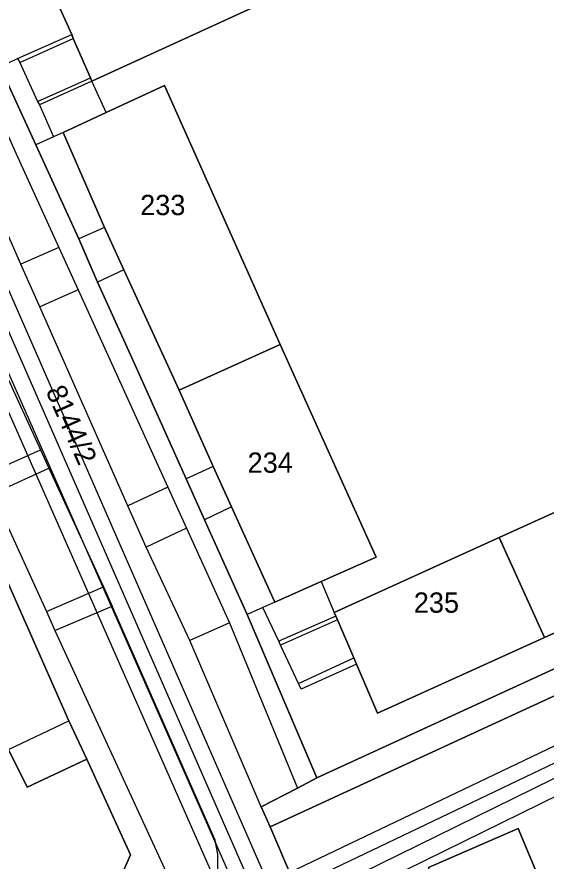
# Model space of a CAD drawing. Extents: x -264070 to -262271, y -1238894 to -1238141.
# Drawn here: x -263532.4 to -263480.2, y -1238522.1 to -1238438.9 of the extents above; entities that cross this region are included whole.
import ezdxf

# ---------------------------------------------------------------- set-up
doc = ezdxf.new("R2010")
doc.units = 0
for name, color, linetype in [('body_kn', 7, 'Continuous'), ('kladpar_druhypozemkov', 7, 'Continuous'), ('kladpar_hranice', 7, 'Continuous'), ('kladpar_parcelnecisla', 7, 'Continuous'), ('kladpar_plochy', 7, 'Continuous'), ('tarchy_linie', 7, 'Continuous'), ('zappar_hrandruhpozemk', 7, 'Continuous')]:
    doc.layers.add(name, color=color, linetype=linetype)

msp = doc.modelspace()

# ---------------------------------------------------------------- linework, layer by layer
at = {"layer": 'body_kn'}
for p, q in [((-263527, -1238440.63), (-263527, -1238440.63)), ((-263526.85, -1238441.05), (-263526.85, -1238441.05)), ((-263532.35, -1238443.02), (-263532.35, -1238443.02)), ((-263532.35, -1238443.02), (-263532.35, -1238443.02)), ((-263532.13, -1238443.41), (-263532.13, -1238443.41)), ((-263525.15, -1238444.9), (-263525.15, -1238444.9)), ((-263525, -1238445.24), (-263525, -1238445.24)), ((-263525, -1238445.24), (-263525, -1238445.24)), ((-263517.86, -1238445.68), (-263517.86, -1238445.68)), ((-263530.38, -1238447.26), (-263530.38, -1238447.26)), ((-263530.19, -1238447.56), (-263530.19, -1238447.56)), ((-263530.19, -1238447.56), (-263530.19, -1238447.56)), ((-263523.6, -1238448.33), (-263523.6, -1238448.33)), ((-263523.6, -1238448.33), (-263523.6, -1238448.33)), ((-263528.79, -1238450.73), (-263528.79, -1238450.73)), ((-263527.83, -1238450.32), (-263527.83, -1238450.32)), ((-263527.83, -1238450.32), (-263527.83, -1238450.32)), ((-263530.53, -1238451.52), (-263530.53, -1238451.52)), ((-263523.77, -1238459.66), (-263523.77, -1238459.66)), ((-263523.77, -1238459.66), (-263523.77, -1238459.66)), ((-263526.3, -1238460.78), (-263526.3, -1238460.78)), ((-263528.28, -1238461.63), (-263528.28, -1238461.63)), ((-263528.28, -1238461.63), (-263528.28, -1238461.63)), ((-263532.01, -1238463.29), (-263532.01, -1238463.29)), ((-263521.86, -1238463.86), (-263521.86, -1238463.86)), ((-263521.86, -1238463.86), (-263521.86, -1238463.86)), ((-263524.45, -1238465.05), (-263524.45, -1238465.05)), ((-263524.45, -1238465.05), (-263524.45, -1238465.05)), ((-263526.38, -1238465.8), (-263526.38, -1238465.8)), ((-263530.15, -1238467.48), (-263530.15, -1238467.48)), ((-263530.15, -1238467.48), (-263530.15, -1238467.48)), ((-263506.44, -1238471.22), (-263506.44, -1238471.22)), ((-263506.44, -1238471.22), (-263506.44, -1238471.22)), ((-263521.05, -1238472.6), (-263521.05, -1238472.6)), ((-263516.41, -1238475.7), (-263516.41, -1238475.7)), ((-263530.08, -1238481.6), (-263530.08, -1238481.6)), ((-263530.08, -1238481.6), (-263530.08, -1238481.6)), ((-263529.25, -1238483.41), (-263529.25, -1238483.41)), ((-263513.04, -1238483.23), (-263513.04, -1238483.23)), ((-263513.04, -1238483.23), (-263513.04, -1238483.23)), ((-263515.71, -1238484.44), (-263515.71, -1238484.44)), ((-263517.52, -1238485.28), (-263517.52, -1238485.28)), ((-263521.45, -1238487.1), (-263521.45, -1238487.1)), ((-263521.45, -1238487.1), (-263521.45, -1238487.1)), ((-263511.23, -1238487.21), (-263511.23, -1238487.21)), ((-263511.23, -1238487.21), (-263511.23, -1238487.21)), ((-263513.9, -1238488.48), (-263513.9, -1238488.48)), ((-263515.69, -1238489.32), (-263515.69, -1238489.32)), ((-263515.69, -1238489.32), (-263515.69, -1238489.32)), ((-263484.82, -1238490.23), (-263484.82, -1238490.23)), ((-263484.82, -1238490.23), (-263484.82, -1238490.23)), ((-263519.64, -1238491.18), (-263519.64, -1238491.18)), ((-263496.95, -1238492.17), (-263496.95, -1238492.17)), ((-263502.38, -1238494.57), (-263502.38, -1238494.57)), ((-263502.38, -1238494.57), (-263502.38, -1238494.57)), ((-263523.88, -1238495.1), (-263523.88, -1238495.1)), ((-263523.01, -1238496.99), (-263523.01, -1238496.99)), ((-263508.14, -1238497.14), (-263508.14, -1238497.14)), ((-263508.14, -1238497.14), (-263508.14, -1238497.14)), ((-263506.96, -1238496.61), (-263506.96, -1238496.61)), ((-263506.96, -1238496.61), (-263506.96, -1238496.61)), ((-263529.5, -1238497.53), (-263529.5, -1238497.53)), ((-263529.5, -1238497.53), (-263529.5, -1238497.53)), ((-263509.7, -1238497.82), (-263509.7, -1238497.82)), ((-263501.1, -1238497.63), (-263501.1, -1238497.63)), ((-263500.94, -1238498), (-263500.94, -1238498)), ((-263500.94, -1238498), (-263500.94, -1238498)), ((-263511.45, -1238498.64), (-263511.45, -1238498.64)), ((-263511.45, -1238498.64), (-263511.45, -1238498.64)), ((-263500.79, -1238498.36), (-263500.79, -1238498.36)), ((-263500.79, -1238498.36), (-263500.79, -1238498.36)), ((-263528.65, -1238499.39), (-263528.65, -1238499.39)), ((-263528.65, -1238499.39), (-263528.65, -1238499.39)), ((-263515.35, -1238500.38), (-263515.35, -1238500.38)), ((-263515.35, -1238500.38), (-263515.35, -1238500.38)), ((-263506.58, -1238500.45), (-263506.58, -1238500.45)), ((-263506.58, -1238500.45), (-263506.58, -1238500.45)), ((-263480.36, -1238500.09), (-263480.36, -1238500.09)), ((-263506.4, -1238500.84), (-263506.4, -1238500.84)), ((-263506.4, -1238500.84), (-263506.4, -1238500.84)), ((-263499.16, -1238502.11), (-263499.16, -1238502.11)), ((-263498.91, -1238502.71), (-263498.91, -1238502.71)), ((-263498.91, -1238502.71), (-263498.91, -1238502.71)), ((-263504.63, -1238504.62), (-263504.63, -1238504.62)), ((-263504.37, -1238505.19), (-263504.37, -1238505.19)), ((-263496.82, -1238507.56), (-263496.82, -1238507.56)), ((-263527.27, -1238508.32), (-263527.27, -1238508.32)), ((-263525.52, -1238512.09), (-263525.52, -1238512.09)), ((-263502.82, -1238513.93), (-263502.82, -1238513.93)), ((-263531.4, -1238514.86), (-263531.4, -1238514.86)), ((-263531.4, -1238514.86), (-263531.4, -1238514.86)), ((-263504.72, -1238514.94), (-263504.72, -1238514.94)), ((-263508.31, -1238516.78), (-263508.31, -1238516.78)), ((-263508.31, -1238516.78), (-263508.31, -1238516.78)), ((-263507.42, -1238518.77), (-263507.42, -1238518.77)), ((-263482.95, -1238518.92), (-263482.95, -1238518.92)), ((-263512.85, -1238520.09), (-263512.85, -1238520.09)), ((-263512.58, -1238521.47), (-263512.58, -1238521.47)), ((-263521.21, -1238521.51), (-263521.21, -1238521.51))]:
    msp.add_line(p, q, dxfattribs=at)
at = {"layer": 'kladpar_druhypozemkov'}
for p, q in [((-263517.76, -1238456.8), (-263517.76, -1238456.8)), ((-263530.05, -1238474.62), (-263530.05, -1238474.62)), ((-263507.71, -1238481.8), (-263507.71, -1238481.8)), ((-263491.11, -1238495.4), (-263491.11, -1238495.4))]:
    msp.add_line(p, q, dxfattribs=at)
at = {"layer": 'kladpar_hranice'}
for points in [[(-263493.11, -1238415.76), (-263470.58, -1238405.55), (-263468.15, -1238404.43), (-263451.66, -1238396.9), (-263450.61, -1238399.35), (-263426.11, -1238459), (-263424.74, -1238462.35), (-263423.38, -1238465.68), (-263422.04, -1238468.97), (-263420.59, -1238472.47), (-263419.19, -1238475.61), (-263423.39, -1238477.55), (-263433.56, -1238482.16), (-263502.82, -1238513.93), (-263509.7, -1238497.82), (-263513.9, -1238488.48), (-263515.71, -1238484.44), (-263521.05, -1238472.6), (-263524.45, -1238465.05), (-263526.3, -1238460.78), (-263530.53, -1238451.52), (-263534.06, -1238443.82)], [(-263474.15, -1238422.1), (-263452.92, -1238412.46), (-263454.93, -1238407.94), (-263450.88, -1238406.06), (-263453.34, -1238400.63), (-263467.07, -1238406.77), (-263469.48, -1238407.89), (-263478.58, -1238412.08), (-263491.98, -1238418.16), (-263494.64, -1238419.36), (-263503.63, -1238423.51), (-263517.17, -1238429.65), (-263519.77, -1238430.84), (-263529.46, -1238435.2), (-263527, -1238440.63), (-263526.85, -1238441.05), (-263525.15, -1238444.9), (-263525, -1238445.24), (-263499.27, -1238433.43), (-263474.15, -1238422.1)], [(-263517.17, -1238429.65), (-263503.63, -1238423.51), (-263499.27, -1238433.43), (-263525, -1238445.24), (-263525.15, -1238444.9), (-263526.85, -1238441.05), (-263527, -1238440.63), (-263529.46, -1238435.2), (-263519.77, -1238430.84), (-263517.17, -1238429.65)], [(-263521.92, -1238523.16), (-263521.21, -1238521.51), (-263525.52, -1238512.09), (-263527.27, -1238508.32), (-263533.94, -1238493.27), (-263540.78, -1238478.21), (-263547.35, -1238463.4), (-263555.82, -1238444.87), (-263548.49, -1238441.32), (-263542.86, -1238438.6), (-263537.75, -1238436.14), (-263534.06, -1238443.82), (-263530.53, -1238451.52), (-263526.3, -1238460.78), (-263524.45, -1238465.05)], [(-263496.95, -1238492.17), (-263506.44, -1238471.22), (-263517.86, -1238445.68), (-263523.6, -1238448.33), (-263527.83, -1238450.32), (-263523.77, -1238459.66), (-263521.86, -1238463.86), (-263516.41, -1238475.7), (-263513.04, -1238483.23), (-263511.23, -1238487.21), (-263506.96, -1238496.61), (-263502.38, -1238494.57), (-263496.95, -1238492.17)], [(-263506.44, -1238471.22), (-263516.41, -1238475.7), (-263521.86, -1238463.86), (-263523.77, -1238459.66), (-263527.83, -1238450.32), (-263523.6, -1238448.33), (-263517.86, -1238445.68), (-263506.44, -1238471.22)], [(-263524.45, -1238465.05), (-263521.05, -1238472.6), (-263515.71, -1238484.44), (-263513.9, -1238488.48), (-263509.7, -1238497.82), (-263502.82, -1238513.93), (-263504.72, -1238514.94), (-263508.31, -1238516.78), (-263507.42, -1238518.77), (-263505.24, -1238523.86)], [(-263459.89, -1238490.81), (-263441.83, -1238482.63), (-263424.56, -1238474.9), (-263428.88, -1238464.9), (-263446.37, -1238472.82), (-263464.41, -1238480.99), (-263484.82, -1238490.23), (-263501.1, -1238497.63), (-263500.94, -1238498), (-263500.79, -1238498.36), (-263499.16, -1238502.11), (-263498.91, -1238502.71), (-263496.82, -1238507.56), (-263480.36, -1238500.09), (-263459.89, -1238490.81)], [(-263506.44, -1238471.22), (-263496.95, -1238492.17), (-263502.38, -1238494.57), (-263506.96, -1238496.61), (-263511.23, -1238487.21), (-263513.04, -1238483.23), (-263516.41, -1238475.7), (-263506.44, -1238471.22)], [(-263464.41, -1238480.99), (-263459.89, -1238490.81), (-263480.36, -1238500.09), (-263484.82, -1238490.23), (-263464.41, -1238480.99)], [(-263433.56, -1238482.16), (-263432.65, -1238484.31), (-263507.42, -1238518.77), (-263508.31, -1238516.78), (-263504.72, -1238514.94), (-263502.82, -1238513.93), (-263433.56, -1238482.16)], [(-263505.24, -1238523.86), (-263507.42, -1238518.77), (-263432.65, -1238484.31)], [(-263484.82, -1238490.23), (-263480.36, -1238500.09), (-263496.82, -1238507.56), (-263498.91, -1238502.71), (-263499.16, -1238502.11), (-263500.79, -1238498.36), (-263500.94, -1238498), (-263501.1, -1238497.63), (-263484.82, -1238490.23)], [(-263533.94, -1238493.27), (-263527.27, -1238508.32), (-263525.52, -1238512.09), (-263531.4, -1238514.86), (-263533.22, -1238511.14), (-263537.53, -1238513.17), (-263538.52, -1238513.67), (-263541.73, -1238506.78), (-263543.34, -1238507.57), (-263545, -1238504.22), (-263543.4, -1238503.43), (-263545.4, -1238499.35), (-263545.75, -1238499.56), (-263546.04, -1238498.93), (-263533.94, -1238493.27)], [(-263531.4, -1238514.86), (-263525.52, -1238512.09), (-263521.21, -1238521.51), (-263521.92, -1238523.16), (-263546.82, -1238534.88), (-263551.68, -1238524.8), (-263543.28, -1238520.85), (-263542.79, -1238521.91), (-263540.78, -1238520.99), (-263541.05, -1238518.89), (-263541.02, -1238518.35), (-263540.78, -1238517.93), (-263540.39, -1238517.72), (-263539.94, -1238517.66), (-263539.28, -1238517.73), (-263538.68, -1238518.03), (-263538.14, -1238518.48), (-263537.45, -1238519.44), (-263535.11, -1238518.3), (-263537.53, -1238513.17), (-263533.22, -1238511.14), (-263531.4, -1238514.86)], [(-263485.85, -1238527.44), (-263494.78, -1238531.48), (-263500.76, -1238534.18), (-263503.51, -1238527.84), (-263497.35, -1238525.17), (-263496.21, -1238527.97), (-263495.08, -1238530.75), (-263489.47, -1238528.04), (-263490.65, -1238525.35), (-263491.8, -1238522.76), (-263482.95, -1238518.92), (-263480.47, -1238524.91), (-263485.85, -1238527.44)], [(-263480.47, -1238524.91), (-263482.95, -1238518.92), (-263491.8, -1238522.76)]]:
    msp.add_lwpolyline(points, dxfattribs=at)
at = {"layer": 'kladpar_plochy'}
for p, q in [((-263525, -1238445.24), (-263499.27, -1238433.43)), ((-263529.46, -1238435.2), (-263527, -1238440.63)), ((-263527, -1238440.63), (-263526.85, -1238441.05)), ((-263526.85, -1238441.05), (-263525.15, -1238444.9)), ((-263530.53, -1238451.52), (-263534.06, -1238443.82)), ((-263525.15, -1238444.9), (-263525, -1238445.24)), ((-263517.86, -1238445.68), (-263523.6, -1238448.33)), ((-263506.44, -1238471.22), (-263517.86, -1238445.68)), ((-263523.6, -1238448.33), (-263527.83, -1238450.32)), ((-263527.83, -1238450.32), (-263523.77, -1238459.66)), ((-263526.3, -1238460.78), (-263530.53, -1238451.52)), ((-263523.77, -1238459.66), (-263521.86, -1238463.86)), ((-263524.45, -1238465.05), (-263526.3, -1238460.78)), ((-263521.86, -1238463.86), (-263516.41, -1238475.7)), ((-263521.05, -1238472.6), (-263524.45, -1238465.05)), ((-263496.95, -1238492.17), (-263506.44, -1238471.22)), ((-263515.71, -1238484.44), (-263521.05, -1238472.6)), ((-263516.41, -1238475.7), (-263513.04, -1238483.23)), ((-263464.41, -1238480.99), (-263484.82, -1238490.23)), ((-263433.56, -1238482.16), (-263502.82, -1238513.93)), ((-263513.04, -1238483.23), (-263511.23, -1238487.21)), ((-263513.9, -1238488.48), (-263515.71, -1238484.44)), ((-263511.23, -1238487.21), (-263506.96, -1238496.61)), ((-263509.7, -1238497.82), (-263513.9, -1238488.48)), ((-263484.82, -1238490.23), (-263501.1, -1238497.63)), ((-263480.36, -1238500.09), (-263459.89, -1238490.81)), ((-263502.38, -1238494.57), (-263496.95, -1238492.17)), ((-263506.96, -1238496.61), (-263502.38, -1238494.57)), ((-263502.82, -1238513.93), (-263509.7, -1238497.82)), ((-263501.1, -1238497.63), (-263500.94, -1238498)), ((-263500.94, -1238498), (-263500.79, -1238498.36)), ((-263500.79, -1238498.36), (-263499.16, -1238502.11)), ((-263496.82, -1238507.56), (-263480.36, -1238500.09)), ((-263499.16, -1238502.11), (-263498.91, -1238502.71)), ((-263498.91, -1238502.71), (-263496.82, -1238507.56))]:
    msp.add_line(p, q, dxfattribs=at)
for points in [[(-263517.17, -1238429.65), (-263503.63, -1238423.51), (-263499.27, -1238433.43), (-263525, -1238445.24), (-263525.15, -1238444.9), (-263526.85, -1238441.05), (-263527, -1238440.63), (-263529.46, -1238435.2), (-263519.77, -1238430.84)], [(-263506.44, -1238471.22), (-263516.41, -1238475.7), (-263521.86, -1238463.86), (-263523.77, -1238459.66), (-263527.83, -1238450.32), (-263523.6, -1238448.33), (-263517.86, -1238445.68)], [(-263506.44, -1238471.22), (-263496.95, -1238492.17), (-263502.38, -1238494.57), (-263506.96, -1238496.61), (-263511.23, -1238487.21), (-263513.04, -1238483.23), (-263516.41, -1238475.7)], [(-263464.41, -1238480.99), (-263459.89, -1238490.81), (-263480.36, -1238500.09), (-263484.82, -1238490.23)], [(-263433.56, -1238482.16), (-263432.65, -1238484.31), (-263507.42, -1238518.77), (-263508.31, -1238516.78), (-263504.72, -1238514.94), (-263502.82, -1238513.93)], [(-263484.82, -1238490.23), (-263480.36, -1238500.09), (-263496.82, -1238507.56), (-263498.91, -1238502.71), (-263499.16, -1238502.11), (-263500.79, -1238498.36), (-263500.94, -1238498), (-263501.1, -1238497.63)], [(-263533.94, -1238493.27), (-263527.27, -1238508.32), (-263525.52, -1238512.09), (-263531.4, -1238514.86), (-263533.22, -1238511.14), (-263537.53, -1238513.17), (-263538.52, -1238513.67), (-263541.73, -1238506.78), (-263543.34, -1238507.57), (-263545, -1238504.22), (-263543.4, -1238503.43), (-263545.4, -1238499.35), (-263545.75, -1238499.56), (-263546.04, -1238498.93)], [(-263531.4, -1238514.86), (-263525.52, -1238512.09), (-263521.21, -1238521.51), (-263521.92, -1238523.16), (-263546.82, -1238534.88), (-263551.68, -1238524.8), (-263543.28, -1238520.85), (-263542.79, -1238521.91), (-263540.78, -1238520.99), (-263541.05, -1238518.89), (-263541.02, -1238518.35), (-263540.78, -1238517.93), (-263540.39, -1238517.72), (-263539.94, -1238517.66), (-263539.28, -1238517.73), (-263538.68, -1238518.03), (-263538.14, -1238518.48), (-263537.45, -1238519.44), (-263535.11, -1238518.3), (-263537.53, -1238513.17), (-263533.22, -1238511.14)], [(-263485.85, -1238527.44), (-263494.78, -1238531.48), (-263500.76, -1238534.18), (-263503.51, -1238527.84), (-263497.35, -1238525.17), (-263496.21, -1238527.97), (-263495.08, -1238530.75), (-263489.47, -1238528.04), (-263490.65, -1238525.35), (-263491.8, -1238522.76), (-263482.95, -1238518.92), (-263480.47, -1238524.91)]]:
    msp.add_lwpolyline(points, close=True, dxfattribs=at)
for points in [[(-263521.92, -1238523.16), (-263521.21, -1238521.51), (-263525.52, -1238512.09), (-263527.27, -1238508.32), (-263533.94, -1238493.27), (-263540.78, -1238478.21), (-263547.35, -1238463.4), (-263555.82, -1238444.87), (-263548.49, -1238441.32), (-263542.86, -1238438.6), (-263537.75, -1238436.14), (-263534.06, -1238443.82), (-263530.53, -1238451.52), (-263526.3, -1238460.78), (-263524.45, -1238465.05), (-263521.05, -1238472.6), (-263515.71, -1238484.44), (-263513.9, -1238488.48), (-263509.7, -1238497.82), (-263502.82, -1238513.93), (-263504.72, -1238514.94), (-263508.31, -1238516.78), (-263507.42, -1238518.77), (-263505.24, -1238523.86)], [(-263505.24, -1238523.86), (-263507.42, -1238518.77), (-263432.65, -1238484.31), (-263433.56, -1238482.16), (-263423.39, -1238477.55), (-263419.19, -1238475.61), (-263420.59, -1238472.47), (-263414.72, -1238470.22), (-263406, -1238466.94), (-263402.83, -1238473.77), (-263403.06, -1238474.31), (-263404.1, -1238475.59), (-263405.07, -1238476.13), (-263402.52, -1238482.03), (-263400.02, -1238481.47), (-263398.6, -1238481.71), (-263397.23, -1238482.35), (-263395.5, -1238483.56), (-263394.88, -1238484.24), (-263405.83, -1238489.45), (-263411.74, -1238492.26), (-263480.04, -1238524.71)], [(-263480.47, -1238524.91), (-263482.95, -1238518.92), (-263491.8, -1238522.76)]]:
    msp.add_lwpolyline(points, dxfattribs=at)
at = {"layer": 'tarchy_linie'}
for p, q in [((-263546.25, -1238440.24), (-263507.83, -1238527.97)), ((-263547.83, -1238441), (-263509.85, -1238527.03))]:
    msp.add_line(p, q, dxfattribs=at)
for points in [[(-263544.77, -1238439.52), (-263507.65, -1238524.27), (-263505.5, -1238523.25), (-263505.24, -1238523.86), (-263504.89, -1238524.66), (-263504.22, -1238526.2), (-263503.57, -1238527.71), (-263507.11, -1238529.51), (-263514.24, -1238532.83), (-263514.94, -1238531.28), (-263515.63, -1238529.75), (-263516.2, -1238528.48), (-263516.27, -1238528.34), (-263511.86, -1238526.28), (-263549.22, -1238441.67), (-263548.49, -1238441.32), (-263547.83, -1238441), (-263546.25, -1238440.24), (-263544.77, -1238439.52)], [(-263505.5, -1238523.25), (-263412.72, -1238478.92), (-263415.25, -1238472.76), (-263405.35, -1238468.34), (-263404.7, -1238469.74), (-263404.05, -1238471.14), (-263411.27, -1238474.36), (-263408.76, -1238480.44), (-263431.07, -1238491.1), (-263430.66, -1238491.93), (-263471.25, -1238511.83), (-263503.57, -1238527.71), (-263504.22, -1238526.2), (-263504.89, -1238524.66), (-263505.5, -1238523.25)], [(-263404.7, -1238469.74), (-263413.26, -1238473.56), (-263410.74, -1238479.68), (-263504.89, -1238524.66)], [(-263432.73, -1238491.11), (-263471.98, -1238510.35), (-263504.22, -1238526.2)]]:
    msp.add_lwpolyline(points, dxfattribs=at)
at = {"layer": 'zappar_hrandruhpozemk'}
for p, q in [((-263532.13, -1238443.41), (-263526.85, -1238441.05)), ((-263532.35, -1238443.02), (-263532.13, -1238443.41)), ((-263532.13, -1238443.41), (-263530.38, -1238447.26)), ((-263530.38, -1238447.26), (-263525.15, -1238444.9)), ((-263525, -1238445.24), (-263530.19, -1238447.56)), ((-263523.6, -1238448.33), (-263525, -1238445.24)), ((-263530.38, -1238447.26), (-263530.19, -1238447.56)), ((-263530.19, -1238447.56), (-263528.79, -1238450.73)), ((-263523.77, -1238459.66), (-263526.3, -1238460.78)), ((-263528.28, -1238461.63), (-263532.01, -1238463.29)), ((-263521.86, -1238463.86), (-263524.45, -1238465.05)), ((-263526.38, -1238465.8), (-263530.15, -1238467.48)), ((-263526.38, -1238465.8), (-263517.52, -1238485.28)), ((-263521.45, -1238487.1), (-263530.15, -1238467.48)), ((-263535.88, -1238468.98), (-263530.08, -1238481.6)), ((-263535.65, -1238484.1), (-263530.08, -1238481.6)), ((-263534.82, -1238485.92), (-263529.25, -1238483.41)), ((-263513.04, -1238483.23), (-263515.71, -1238484.44)), ((-263517.52, -1238485.28), (-263521.45, -1238487.1)), ((-263511.23, -1238487.21), (-263513.9, -1238488.48)), ((-263515.69, -1238489.32), (-263519.64, -1238491.18)), ((-263502.38, -1238494.57), (-263501.1, -1238497.63)), ((-263529.5, -1238497.53), (-263523.88, -1238495.1)), ((-263528.65, -1238499.39), (-263523.01, -1238496.99)), ((-263512.85, -1238520.09), (-263523.01, -1238496.99)), ((-263508.14, -1238497.14), (-263509.7, -1238497.82)), ((-263506.96, -1238496.61), (-263508.14, -1238497.14)), ((-263506.58, -1238500.45), (-263508.14, -1238497.14)), ((-263500.94, -1238498), (-263506.58, -1238500.45)), ((-263511.45, -1238498.64), (-263515.35, -1238500.38)), ((-263511.45, -1238498.64), (-263504.72, -1238514.94)), ((-263500.79, -1238498.36), (-263506.4, -1238500.84)), ((-263528.65, -1238499.39), (-263515.48, -1238527.97)), ((-263508.31, -1238516.78), (-263515.35, -1238500.38)), ((-263506.4, -1238500.84), (-263506.58, -1238500.45)), ((-263504.63, -1238504.62), (-263506.4, -1238500.84)), ((-263504.63, -1238504.62), (-263499.16, -1238502.11)), ((-263533.22, -1238511.14), (-263527.27, -1238508.32))]:
    msp.add_line(p, q, dxfattribs=at)
for points in [[(-263541.93, -1238440.73), (-263538.47, -1238439.21), (-263534.32, -1238448.32), (-263532.47, -1238452.4), (-263528.28, -1238461.63), (-263526.38, -1238465.8)], [(-263530.15, -1238467.48), (-263532.01, -1238463.29), (-263536.11, -1238454.05), (-263537.93, -1238449.95), (-263541.93, -1238440.73)], [(-263534.06, -1238443.82), (-263532.35, -1238443.02), (-263527, -1238440.63)], [(-263527.83, -1238450.32), (-263528.79, -1238450.73), (-263530.53, -1238451.52)], [(-263530.08, -1238481.6), (-263529.25, -1238483.41), (-263523.88, -1238495.1), (-263523.01, -1238496.99)], [(-263535.65, -1238484.1), (-263534.82, -1238485.92), (-263529.5, -1238497.53), (-263528.65, -1238499.39)], [(-263517.52, -1238485.28), (-263515.69, -1238489.32), (-263511.45, -1238498.64)], [(-263515.35, -1238500.38), (-263519.64, -1238491.18), (-263521.45, -1238487.1)], [(-263498.91, -1238502.71), (-263504.37, -1238505.19), (-263504.63, -1238504.62)], [(-263516.2, -1238528.48), (-263515.48, -1238527.97), (-263513.88, -1238526.62), (-263513.19, -1238525.46), (-263512.71, -1238524.17), (-263512.59, -1238522.85), (-263512.58, -1238521.47), (-263512.85, -1238520.09)]]:
    msp.add_lwpolyline(points, dxfattribs=at)

# ---------------------------------------------------------------- texts
at = {"layer": 'kladpar_parcelnecisla'}
for s, p in [('233', (-263520.25, -1238458.45)), ('234', (-263509.648, -1238483.85)), ('235', (-263493.253, -1238497.65))]:
    msp.add_text(s, height=2, dxfattribs=at).set_placement(p)
msp.add_text('8144/2', height=2, rotation=294, dxfattribs=at).set_placement((-263529.598, -1238475.782))

doc.saveas('drawing.dxf')
